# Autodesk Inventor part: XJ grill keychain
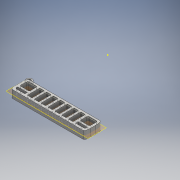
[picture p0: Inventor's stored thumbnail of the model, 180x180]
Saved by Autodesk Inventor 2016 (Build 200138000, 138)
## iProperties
Created: 2018-02
Part Number: XJ grill keychain
Material: Generic
Document SubType Name: Modeling
Designer: John
Density: 1 g/cm^3
Appearance: Default
Author: John
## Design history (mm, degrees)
sketch "Sketch1"
  geometry: L1 (241.033, -72.509)-(244.917, -72.509); L2 (245.367, -72.959)-(245.367, -84.832); L3 (244.917, -85.282)-(241.033, -85.282); L4 (240.583, -84.832)-(240.583, -72.959); L5 (227.623, -70.485)-(300.651, -70.485); L6 (300.651, -87.809)-(227.623, -87.809); L7 (225.849, -82.174)-(225.849, -76.539); L8 (229.31, -72.509)-(236.98, -72.509); L9 (238.08, -73.609)-(238.08, -79.557); L10 (236.98, -80.657)-(229.31, -80.657); L11 (228.21, -79.557)-(228.21, -73.609); L12 (238.08, -82.72)-(228.21, -82.72); L13 (228.21, -82.72)-(228.21, -84.182); L14 (229.31, -85.282)-(238.08, -85.282); L15 (238.08, -85.282)-(238.08, -82.72); L16 (225.849, -82.174)-(225.983, -85.151); L17 (225.983, -85.151)-(226.224, -86.471); L18 (226.224, -86.471)-(226.816, -87.277); L19 (226.816, -87.277)-(227.103, -87.73); L20 (227.103, -87.73)-(227.623, -87.809); L21 (248.053, -72.509)-(251.937, -72.509); L22 (247.603, -84.832)-(247.603, -72.959); L23 (252.387, -72.959)-(252.387, -84.832); L24 (251.937, -85.282)-(248.053, -85.282); L25 (255.057, -72.509)-(258.942, -72.509); L26 (254.607, -84.832)-(254.607, -72.959); L27 (259.392, -72.959)-(259.392, -84.832); L28 (258.942, -85.282)-(255.057, -85.282); L29 (262.195, -72.509)-(266.079, -72.509); L30 (261.745, -84.832)-(261.745, -72.959); L31 (266.529, -72.959)-(266.529, -84.832); L32 (266.079, -85.282)-(262.195, -85.282); L33 (269.338, -72.509)-(273.222, -72.509); L34 (268.888, -84.832)-(268.888, -72.959); L35 (273.672, -72.959)-(273.672, -84.832); L36 (273.222, -85.282)-(269.338, -85.282); L37 (276.34, -72.588)-(280.224, -72.588); L38 (275.89, -84.911)-(275.89, -73.038); L39 (280.674, -73.038)-(280.674, -84.911); L40 (280.224, -85.361)-(276.34, -85.361); L41 (283.346, -72.588)-(287.23, -72.588); L42 (282.896, -84.911)-(282.896, -73.038); L43 (287.68, -73.038)-(287.68, -84.911); L44 (287.23, -85.361)-(283.346, -85.361); L45 (302.425, -82.174)-(302.425, -76.539); L46 (302.425, -82.174)-(302.291, -85.151); L47 (302.291, -85.151)-(302.05, -86.471); L48 (302.05, -86.471)-(301.458, -87.277); L49 (301.458, -87.277)-(301.171, -87.73); L50 (301.171, -87.73)-(300.651, -87.809); L51 (300.064, -82.72)-(300.064, -84.182); L52 (290.194, -82.72)-(300.064, -82.72); L53 (290.194, -85.282)-(290.194, -82.72); L54 (298.964, -85.282)-(290.194, -85.282); L55 (291.294, -80.657)-(298.964, -80.657); L56 (290.194, -73.609)-(290.194, -79.557); L57 (298.964, -72.509)-(291.294, -72.509); L58 (300.064, -79.557)-(300.064, -73.609); L59 (302.445, -72.509)-(302.445, -72.588); L60 (302.445, -80.657)-(302.445, -82.72); L61 (302.445, -85.282)-(302.445, -85.361); A1 r 0.45 centre (241.033, -72.959) between (241.033, -72.509) and (240.583, -72.959); A2 r 0.45 centre (244.917, -72.959) between (245.367, -72.959) and (244.917, -72.509); A3 r 0.45 centre (244.917, -84.832) between (244.917, -85.282) and (245.367, -84.832); A4 r 0.45 centre (241.033, -84.832) between (240.583, -84.832) and (241.033, -85.282); A5 r 1.1 centre (229.31, -73.609) between (229.31, -72.509) and (228.21, -73.609); A6 r 1.1 centre (236.98, -73.609) between (238.08, -73.609) and (236.98, -72.509); A7 r 1.1 centre (236.98, -79.557) between (236.98, -80.657) and (238.08, -79.557); A8 r 1.1 centre (229.31, -79.557) between (228.21, -79.557) and (229.31, -80.657); A9 r 1.1 centre (229.31, -84.182) between (228.21, -84.182) and (229.31, -85.282); A10 r 0.45 centre (248.053, -72.959) between (248.053, -72.509) and (247.603, -72.959); A11 r 0.45 centre (251.937, -72.959) between (252.387, -72.959) and (251.937, -72.509); A12 r 0.45 centre (251.937, -84.832) between (251.937, -85.282) and (252.387, -84.832); A13 r 0.45 centre (248.053, -84.832) between (247.603, -84.832) and (248.053, -85.282); A14 r 0.45 centre (255.057, -72.959) between (255.057, -72.509) and (254.607, -72.959); A15 r 0.45 centre (258.942, -72.959) between (259.392, -72.959) and (258.942, -72.509); A16 r 0.45 centre (258.942, -84.832) between (258.942, -85.282) and (259.392, -84.832); A17 r 0.45 centre (255.057, -84.832) between (254.607, -84.832) and (255.057, -85.282); A18 r 0.45 centre (262.195, -72.959) between (262.195, -72.509) and (261.745, -72.959); A19 r 0.45 centre (266.079, -72.959) between (266.529, -72.959) and (266.079, -72.509); A20 r 0.45 centre (266.079, -84.832) between (266.079, -85.282) and (266.529, -84.832); A21 r 0.45 centre (262.195, -84.832) between (261.745, -84.832) and (262.195, -85.282); A22 r 0.45 centre (269.338, -72.959) between (269.338, -72.509) and (268.888, -72.959); A23 r 0.45 centre (273.222, -72.959) between (273.672, -72.959) and (273.222, -72.509); A24 r 0.45 centre (273.222, -84.832) between (273.222, -85.282) and (273.672, -84.832); A25 r 0.45 centre (269.338, -84.832) between (268.888, -84.832) and (269.338, -85.282); A26 r 0.45 centre (276.34, -73.038) between (276.34, -72.588) and (275.89, -73.038); A27 r 0.45 centre (280.224, -73.038) between (280.674, -73.038) and (280.224, -72.588); A28 r 0.45 centre (280.224, -84.911) between (280.224, -85.361) and (280.674, -84.911); A29 r 0.45 centre (276.34, -84.911) between (275.89, -84.911) and (276.34, -85.361); A30 r 0.45 centre (283.346, -73.038) between (283.346, -72.588) and (282.896, -73.038); A31 r 0.45 centre (287.23, -73.038) between (287.68, -73.038) and (287.23, -72.588); A32 r 0.45 centre (287.23, -84.911) between (287.23, -85.361) and (287.68, -84.911); A33 r 0.45 centre (283.346, -84.911) between (282.896, -84.911) and (283.346, -85.361); A34 r 1.1 centre (298.964, -84.182) between (298.964, -85.282) and (300.064, -84.182); A35 r 1.1 centre (291.294, -79.557) between (290.194, -79.557) and (291.294, -80.657); A36 r 1.1 centre (291.294, -73.609) between (291.294, -72.509) and (290.194, -73.609); A37 r 1.1 centre (298.964, -73.609) between (300.064, -73.609) and (298.964, -72.509); A38 r 1.1 centre (298.964, -79.557) between (298.964, -80.657) and (300.064, -79.557); 4 further points
  constraints: 102 end point, 76 point on circle, 66 tangent, 38 centre point, 22 parallel, 16 equal radius, 12 perpendicular, 10 horizontal, 9 collinear, 8 point on line, 16 other
  dimensions: "d41" = 0.45 radius of A1; "d42" = 0.45 radius of A2; "d46" = 4.7841 distance between parallel lines of L4 L2; "d111" = 1.1 radius of A5; "d112" = 1.1 radius of A6; "d116" = 1.1 radius of A9; "d127" = 0.45 radius of A10; "d128" = 0.45 radius of A11; "d130" = 4.7841 distance between parallel lines of L22 L23; "d132" = 0.45 radius of A14; "d133" = 0.45 radius of A15; "d135" = 4.7841 distance between parallel lines of L26 L27; "d137" = 0.45 radius of A18; "d138" = 0.45 radius of A19; "d140" = 4.7841 distance between parallel lines of L30 L31; "d142" = 0.45 radius of A22; "d143" = 0.45 radius of A23; "d145" = 4.7841 distance between parallel lines of L34 L35; "d147" = 0.45 radius of A26; "d148" = 0.45 radius of A27; "d150" = 4.7841 distance between parallel lines of L38 L39; "d152" = 0.45 radius of A30; "d153" = 0.45 radius of A31; "d155" = 4.7841 distance between parallel lines of L42 L43
extrude "Extrusion1" new body sketch "Sketch1" distance "d158" = 8; taper "d159" = 0 deg
sketch "Sketch2"
  geometry: 1 further point
workplane "Work Plane1"
sketch "Sketch3"
  geometry: L1 (229.067, -67.98)-(230.134, -70.615); L2 (223.693, -70.615)-(225.895, -74.031); L3 (225.895, -74.031)-(230.134, -70.615); C1 r 1.75 at (226.286, -69.106); A1 r 3 centre (226.286, -69.106) between (229.067, -67.98) and (223.693, -70.615); 1 further point
  constraints: 6 end point, 2 centre point, 2 point on circle, 1 coincident
  dimensions: "d161" = 3.5 diameter of C1; "d162" = 6 diameter of A1
extrude "Extrusion3" join sketch "Sketch3" stored distance "d165" = 4; taper "d166" = 0 deg
body "Solid1"
other parameters: "d92" = 76.59553, "d160" = -4
